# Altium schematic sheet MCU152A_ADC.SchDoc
size 431 x 279 mm; Date: Not shown in title block; ApprovedBy: Not shown in title block; CheckedBy: Not shown in title block; Author: Not shown in title block; CompanyName: Not shown in title block; Engineer: Not shown in title block; Organization: Not shown in title block; Address1: Not shown in title block; Address2: Not shown in title block; Address3: Not shown in title block; Address4: Not shown in title block; DocumentNumber: 5; Revision: Use project parameter SCH_Rev; SheetNumber: 5; SheetTotal: 8; PageSetup: Record=PageOptions¦CenterHorizontal=True¦CenterVertical=True¦PrintScale=1.00¦XCorrection=1.00¦YCorrection=1.00¦PrintKind=0¦BorderSize=5000000¦LeftOffset=0¦BottomOffset=0¦Orientation=2¦PaperLength=1000¦PaperWidth=1000¦Scale=100¦PaperSource=15¦PrintQuality=600¦MediaType=1¦DitherType=10¦PaperKind=Letter¦PrintScaleMode=1
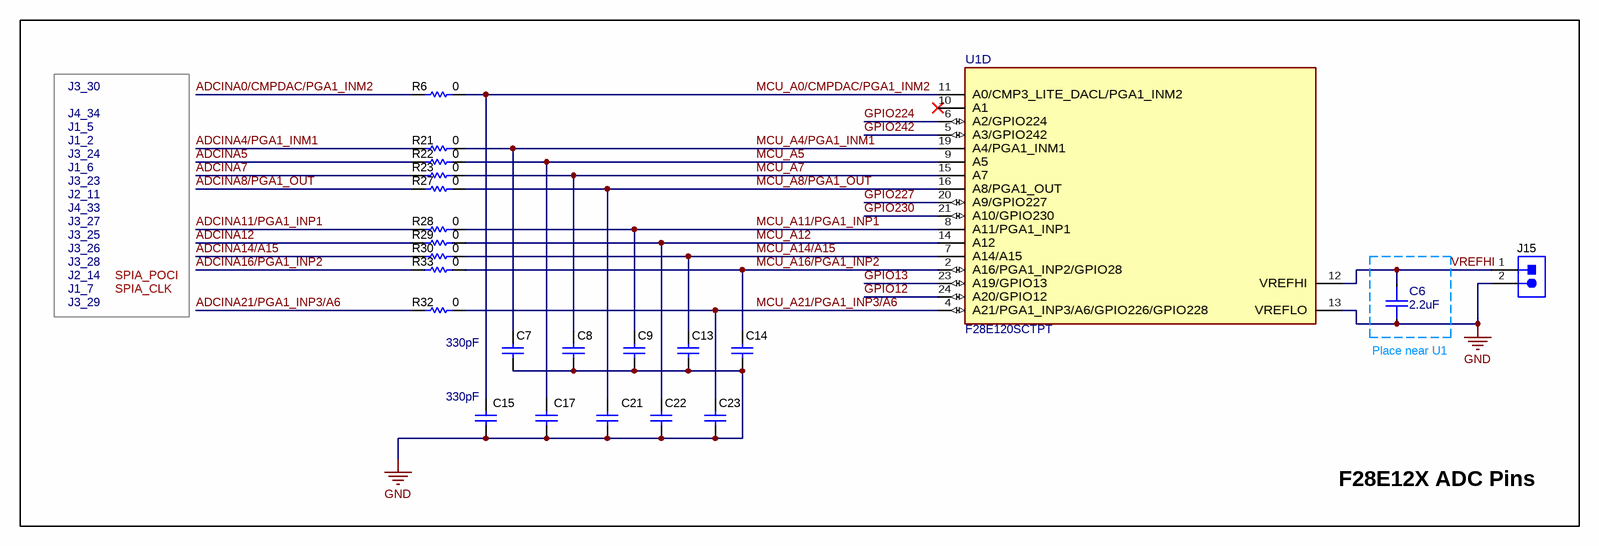
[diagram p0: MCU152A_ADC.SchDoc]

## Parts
C6  ValueDisplayed: 2.2uF  [FP-885012106011_0603-MFG]  (hidden comment: 885012106011)
C7  value 330pF  [0402]  (hidden comment: GRM1555C1H331JA01D)
C8  GRM1555C1H331JA01D  [0402]  (value not drawn)
C9  GRM1555C1H331JA01D  [0402]  (value not drawn)
C13  GRM1555C1H331JA01D  [0402]  (value not drawn)
C14  GRM1555C1H331JA01D  [0402]  (value not drawn)
C15  value 330pF  [0402]  (hidden comment: GRM1555C1H331JA01D)
C17  GRM1555C1H331JA01D  [0402]  (value not drawn)
C21  GRM1555C1H331JA01D  [0402]  (value not drawn)
C22  GRM1555C1H331JA01D  [0402]  (value not drawn)
C23  GRM1555C1H331JA01D  [0402]  (value not drawn)
J15  61300211121  [WURTH_61300211121]  (value not drawn)
R6  ValueDisplayed: 0  [0402]  (hidden comment: RC0402JR-070RL)
R21  ValueDisplayed: 0  [0402]  (hidden comment: RC0402JR-070RL)
R22  ValueDisplayed: 0  [0402]  (hidden comment: RC0402JR-070RL)
R23  ValueDisplayed: 0  [0402]  (hidden comment: RC0402JR-070RL)
R27  ValueDisplayed: 0  [0402]  (hidden comment: RC0402JR-070RL)
R28  ValueDisplayed: 0  [0402]  (hidden comment: RC0402JR-070RL)
R29  ValueDisplayed: 0  [0402]  (hidden comment: RC0402JR-070RL)
R30  ValueDisplayed: 0  [0402]  (hidden comment: RC0402JR-070RL)
R32  ValueDisplayed: 0  [0402]  (hidden comment: RC0402JR-070RL)
R33  ValueDisplayed: 0  [0402]  (hidden comment: RC0402JR-070RL)
U1  F28E120SCTPT  [PT0048A-MFG]  (part D of 4)

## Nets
GND: C6.2 C7.2 C8.2 C9.2 C13.2 C14.2 C15.2 C17.2 C21.2 C22.2 C23.2 J15.2 U1.13(VREFLO)
ADCINA0/CMPDAC/PGA1_INM2: R6.1
ADCINA4/PGA1_INM1: R21.1
ADCINA5: R22.1
ADCINA7: R23.1
ADCINA8/PGA1_OUT: R27.1
ADCINA11/PGA1_INP1: R28.1
ADCINA12: R29.1
ADCINA14/A15: R30.1
ADCINA16/PGA1_INP2: R33.1
ADCINA21/PGA1_INP3/A6: R32.1
GPIO12: U1.24(A20/GPIO12)
GPIO13: U1.23(A19/GPIO13)
GPIO224: U1.6(A2/GPIO224)
GPIO227: U1.20(A9/GPIO227)
GPIO230: U1.21(A10/GPIO230)
GPIO242: U1.5(A3/GPIO242)
MCU_A0/CMPDAC/PGA1_INM2: C15.1 R6.2 U1.11(A0/CMP3_LITE_DACL/PGA1_INM2)
MCU_A4/PGA1_INM1: C7.1 R21.2 U1.19(A4/PGA1_INM1)
MCU_A5: C17.1 R22.2 U1.9(A5)
MCU_A7: C8.1 R23.2 U1.15(A7)
MCU_A8/PGA1_OUT: C21.1 R27.2 U1.16(A8/PGA1_OUT)
MCU_A11/PGA1_INP1: C9.1 R28.2 U1.8(A11/PGA1_INP1)
MCU_A12: C22.1 R29.2 U1.14(A12)
MCU_A14/A15: C13.1 R30.2 U1.7(A14/A15)
MCU_A16/PGA1_INP2: C14.1 R33.2 U1.2(A16/PGA1_INP2/GPIO28)
MCU_A21/PGA1_INP3/A6: C23.1 R32.2 U1.4(A21/PGA1_INP3/A6/GPIO226/GPIO228)
VREFHI: C6.1 J15.1 U1.12(VREFHI)

Not connected (* = marked no-connect by the designer): U1 10(A1)*

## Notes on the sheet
- J3_30
- J4_34
- J1_5
- J3_23
- J1_6
- J1_2
- J3_24
- J3_27
- J3_26
- J3_25
- J3_28
- J2_11
- J4_33
- J3_29
- J1_7
- J2_14
- SPIA_CLK
- SPIA_POCI
- (near C6) Place near U1
- F28E12X ADC Pins

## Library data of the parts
C6 = CMP-0124925-1: 2.2 µF ±20% 10V Ceramic Capacitor X5R 0603 (1608 Metric); Manufacturer: Wurth Electronics; AEC Qualified: No; Cap_F: 2.2µF; SizeZ_mm: 0.87mm; TempCo: 15%; Value: 2.2µF
C7 C15 = CMP-0006456-2: CAP, CERM, 330 pF, 50 V, +/- 5%, C0G/NP0, 0402; Manufacturer: MuRata; TaMin_C: -55°C; Polarized: N; SizeAreaWB_mm2: 3; Value1: Unknown; U/M: EA; TaMax_C: 125°C; SizeZ_mm: 0.6; SizeX_mm: 1; SizeY_mm: 0.5; Value2: 50V; AEC Category: Q200
C8 C9 C13 C14 C17 C21-C23 = CMP-0006456-2: CAP, CERM, 330 pF, 50 V, +/- 5%, C0G/NP0, 0402; Manufacturer: MuRata; TaMin_C: -55°C; Polarized: N; SizeAreaWB_mm2: 3; Value1: Unknown; U/M: EA; Value: 330pF; TaMax_C: 125°C; SizeZ_mm: 0.6; SizeX_mm: 1; SizeY_mm: 0.5; Value2: 50V; AEC Category: Q200
J15 = CMP-0054794-1: Header, 2.54 mm, 2x1, Gold, TH; Manufacturer: Wurth Elektronik; Green_Lifecycle: Active; Green_REACh: Passed; CNHeader: TRUE; CT: FALSE
R6 R21-R23 R27-R30 R32 R33 = CMP-0027004-2: RES, 0, 5%, 0.063 W, 0402; Manufacturer: Yageo America; Power_W: 63mW; TempCo: 200 ppm/C; Value_Code: 0000; U/M: EA; Value: 0; EIA_Code: E24; SizeX_mm: 1; SizeY_mm: 0.5; SizeZ_mm: 0.6; Value2: 0.063W; VDC_V: 50V; AEC Category: Q200
U1 = CMP-0125361-1: F28E12x Real-Time Microcontrollers; Manufacturer: Texas Instruments; SizeZ_mm: 1.6mm; Core Architecture: C28x; Data Bus Width: 32bits; Frequency_Fixed: 160MHz; Interface: I2C,SPI,UART,SCI; Max Supply Voltage: 3.63V; Memory Size: 128KBytes; Memory Type: FLASH; Min Supply Voltage: 2.8V; Number Of A/D Converters: 1; Number Of Adc Channels: 9; Number Of I/Os: 27; Number Of Pwm Channels: 8; Number Of Timers/Counters: 4; Number Of Uart Channels: 2; Ram Size: 16KBytes; Standoff Height: 0.05mm; TJmax_C: +125°C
